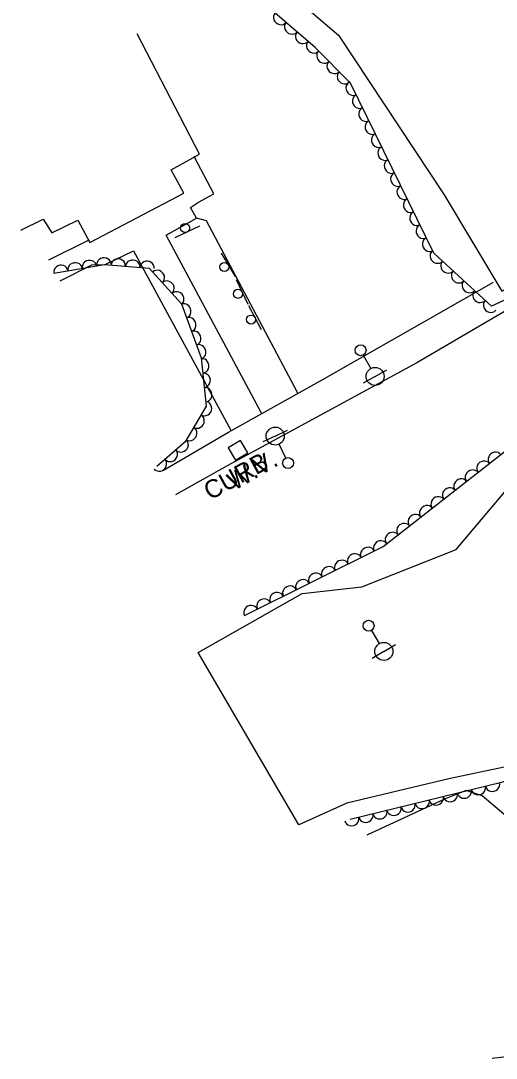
# Model space of a CAD drawing. Extents: x 1722896 to 1754269, y 648279 to 666297.
# Drawn here: x 1725162.1 to 1725293.4, y 656748.7 to 657035.2 of the extents above; entities that cross this region are included whole.
import ezdxf

# ---------------------------------------------------------------- set-up
doc = ezdxf.new("R2010")
doc.units = 0
for name, color, linetype in [('DESIGN - CENTERLINE - Proposed Text', 7, 'Continuous'), ('DESIGN - CONTOURS - Intermediate with optional Text', 7, 'Continuous'), ('DESIGN - PUBLIC HEARING - Shapes', 7, 'Continuous'), ('DESIGN - SCRATCH - User 1', 7, 'Continuous'), ('SURVEY - CENTERLINE - Preliminary', 7, 'Continuous'), ('SURVEY - CENTERLINE - Preliminary Text', 7, 'Continuous'), ('SURVEY - DTM - Breaklines', 7, 'Continuous'), ('SURVEY - VEGETATION - Features with Text', 7, 'Continuous')]:
    doc.layers.add(name, color=color, linetype=linetype)

msp = doc.modelspace()

# ---------------------------------------------------------------- linework, layer by layer
at = {"layer": 'DESIGN - CENTERLINE - Proposed Text'}
for points in [[(1725162.09, 656977.34), (1725168.28, 656980.41), (1725170.64, 656976.67), (1725177.81, 656980.17), (1725181.14, 656973.93), (1725207.11, 656987.54), (1725203.61, 656994.04), (1725211.4, 656998.37), (1725194.22, 657031.57)], [(1725228.55, 656926.87), (1725202.28, 656976), (1725210.6, 656980.65)], [(1725180.74, 656974.47), (1725169.79, 656969.12)], [(1725172.97, 656963.35), (1725181.68, 656967.82), (1725185.43, 656967.84), (1725193.25, 656971.63), (1725220.09, 656922.12)]]:
    msp.add_lwpolyline(points, dxfattribs=at)
at = {"layer": 'DESIGN - CONTOURS - Intermediate with optional Text'}
msp.add_line((1725222.08, 656916.58), (1725222.08, 656916.58), dxfattribs=at)
msp.add_lwpolyline([(1725219.35, 656917.31), (1725221.36, 656913.85), (1725224.81, 656915.86), (1725222.8, 656919.32), (1725219.35, 656917.31)], dxfattribs=at)
at = {"layer": 'DESIGN - PUBLIC HEARING - Shapes'}
for p, q in [((1725211.41, 656978.48), (1725204.65, 656975.24)), ((1725217.41, 656971.04), (1725221.27, 656964.61)), ((1725221.53, 656963.72), (1725224.78, 656956.97)), ((1725225.01, 656956.6), (1725228.51, 656949.97))]:
    msp.add_line(p, q, dxfattribs=at)
for centre in [(1725207.48, 656977.95), (1725218.3, 656967.17), (1725222.06, 656959.79), (1725225.69, 656952.69)]:
    msp.add_circle(centre, 1.25, dxfattribs=at)
at = {"layer": 'SURVEY - CENTERLINE - Preliminary'}
for points in [[(1725220.54, 657056.26), (1725249.82, 657031.18), (1725278.99, 656987.08), (1725294.93, 656960.48), (1725337.04, 656984.32), (1725355.92, 657002.3), (1725347.36, 657029.47), (1725333.65, 657057.33), (1725305.29, 657085.49), (1725285.46, 657108.75), (1725220.54, 657056.26)], [(1725211.04, 656860.76), (1725239.8, 656877.05), (1725256.25, 656878.92), (1725282.33, 656889.19), (1725301.73, 656912.24), (1725311.42, 656915.4), (1725338.36, 656911.9), (1725359.19, 656920.36), (1725368.5, 656904.89), (1725371.6, 656887.76), (1725358.67, 656881.14), (1725359.34, 656873.97), (1725339.38, 656862.59), (1725318.48, 656837.72), (1725302.51, 656830.54), (1725280.24, 656825.91), (1725252.08, 656819.18), (1725238.91, 656813.19), (1725211.04, 656860.76)]]:
    msp.add_lwpolyline(points, dxfattribs=at)
at = {"layer": 'SURVEY - CENTERLINE - Preliminary Text'}
for points in [[(1725549.38, 657135.48), (1725513.49, 657105.3), (1725471.68, 657072.67), (1725427.12, 657040.14), (1725377.39, 657005.82), (1725326.06, 656972.7), (1725271.47, 656940.69), (1725219.07, 656912.28), (1725204.85, 656904.26)], [(1725238.57, 656932.39), (1725213.34, 656979.93), (1725210.6, 656980.65), (1725209, 656983.6), (1725211.15, 656985.14), (1725215.42, 656987.35), (1725209.99, 656997.69)], [(1725201.52, 656911.09), (1725219.49, 656921.62), (1725245.31, 656936.04), (1725292.65, 656963)], [(1725464.13, 656811.54), (1725461.25, 656806.55), (1725458.02, 656803.74), (1725452.12, 656800.11), (1725438.36, 656794.63), (1725409.39, 656783.36), (1725391.32, 656778.7), (1725375, 656774.89), (1725367.83, 656774.04), (1725357.16, 656776.48), (1725342.38, 656782.53), (1725327.16, 656789.64), (1725318.33, 656796.85), (1725296.64, 656815.15), (1725289.47, 656821.17), (1725285.09, 656822.64), (1725279.04, 656820.25), (1725257.65, 656810.3)], [(1725292.23, 656748.73), (1725327.95, 656752.98), (1725364.89, 656756.8), (1725375.48, 656758.16)]]:
    msp.add_lwpolyline(points, dxfattribs=at)
at = {"layer": 'SURVEY - DTM - Breaklines'}
for p, q in [((1725256.65, 656942.89), (1725258.71, 656939.17)), ((1725259.92, 656936.98), (1725256.64, 656935.16)), ((1725259.92, 656936.98), (1725263.2, 656938.8)), ((1725232.34, 656920.5), (1725235.72, 656922.12)), ((1725232.34, 656920.5), (1725228.96, 656918.88)), ((1725235.25, 656914.41), (1725233.42, 656918.24)), ((1725258.91, 656866.86), (1725261.07, 656863.2)), ((1725262.34, 656861.05), (1725265.57, 656862.95)), ((1725262.34, 656861.05), (1725259.11, 656859.14))]:
    msp.add_line(p, q, dxfattribs=at)
for centre, radius in [((1725255.92, 656944.2), 1.5), ((1725259.92, 656936.98), 2.5), ((1725232.34, 656920.5), 2.5), ((1725235.9, 656913.06), 1.5), ((1725258.14, 656868.15), 1.5), ((1725262.34, 656861.05), 2.5)]:
    msp.add_circle(centre, radius, dxfattribs=at)
at = {"layer": 'SURVEY - VEGETATION - Features with Text'}
for points in [[(1725291.18, 657111.91), (1725326.1, 657083.38), (1725337.26, 657071.03), (1725346.29, 657049.3), (1725355.28, 657027.04), (1725360.66, 657009.82), (1725362.75, 657000.18), (1725357.16, 656991.63), (1725326.61, 656972.27), (1725292.02, 656956.35), (1725276.1, 656971.03), (1725253.1, 657017.98), (1725243.39, 657027.79), (1725217.32, 657050.26)], [(1725171.21, 656965.51), (1725185.21, 656967.86), (1725197.58, 656966.88), (1725206.46, 656957.06), (1725211.92, 656942.13), (1725213.32, 656928.75), (1725207.46, 656918.95), (1725199.7, 656912.09)], [(1725223.84, 656870.98), (1725262.11, 656890.03), (1725301.76, 656920.92), (1725328.71, 656923.12), (1725345.82, 656924.48), (1725360.29, 656925.54), (1725367.44, 656920.28), (1725373.75, 656898.57), (1725375.2, 656885.23), (1725358.4, 656869.39), (1725340.72, 656860.08), (1725318.94, 656834.01), (1725294.8, 656824.9), (1725253.01, 656814.68)]]:
    msp.add_lwpolyline(points, dxfattribs=at)
for centre, major_axis in [((1725233.83, 657036.03), (-1.52, 1.31)), ((1725236.86, 657033.42), (-1.52, 1.31)), ((1725239.89, 657030.81), (-1.52, 1.31)), ((1725242.92, 657028.2), (-1.52, 1.31)), ((1725245.77, 657025.39), (-1.41, 1.42)), ((1725248.58, 657022.54), (-1.41, 1.42)), ((1725251.39, 657019.7), (-1.41, 1.42)), ((1725253.79, 657016.56), (-0.88, 1.8)), ((1725255.55, 657012.97), (-0.88, 1.8)), ((1725257.31, 657009.38), (-0.88, 1.8)), ((1725259.07, 657005.79), (-0.88, 1.8)), ((1725260.83, 657002.19), (-0.88, 1.8)), ((1725262.59, 656998.6), (-0.88, 1.8)), ((1725264.35, 656995.01), (-0.88, 1.8)), ((1725266.11, 656991.42), (-0.88, 1.8)), ((1725267.87, 656987.83), (-0.88, 1.8)), ((1725269.63, 656984.23), (-0.88, 1.8)), ((1725271.39, 656980.64), (-0.88, 1.8)), ((1725273.15, 656977.05), (-0.88, 1.8)), ((1725274.91, 656973.46), (-0.88, 1.8)), ((1725277.05, 656970.15), (-1.47, 1.36)), ((1725177.12, 656966.5), (1.97, 0.33)), ((1725181.07, 656967.16), (1.97, 0.33)), ((1725185.01, 656967.83), (1.97, 0.33)), ((1725189, 656967.56), (1.99, -0.16)), ((1725192.99, 656967.24), (1.99, -0.16)), ((1725196.97, 656966.93), (1.99, -0.16)), ((1725279.99, 656967.44), (-1.47, 1.36)), ((1725173.18, 656965.84), (1.97, 0.33)), ((1725199.86, 656964.36), (1.34, -1.48)), ((1725282.93, 656964.73), (-1.47, 1.36)), ((1725202.54, 656961.4), (1.34, -1.48)), ((1725285.88, 656962.02), (-1.47, 1.36)), ((1725205.22, 656958.43), (1.34, -1.48)), ((1725288.82, 656959.31), (-1.47, 1.36)), ((1725207.2, 656955.04), (0.69, -1.88)), ((1725291.76, 656956.6), (-1.47, 1.36)), ((1725208.57, 656951.28), (0.69, -1.88)), ((1725209.95, 656947.53), (0.69, -1.88)), ((1725211.32, 656943.77), (0.69, -1.88)), ((1725212.16, 656939.89), (0.21, -1.99)), ((1725212.57, 656935.91), (0.21, -1.99)), ((1725212.99, 656931.93), (0.21, -1.99)), ((1725212.91, 656928.06), (-1.03, -1.72)), ((1725210.86, 656924.63), (-1.03, -1.72)), ((1725208.8, 656921.2), (-1.03, -1.72)), ((1725206.42, 656918.04), (-1.5, -1.33)), ((1725203.43, 656915.39), (-1.5, -1.33)), ((1725200.43, 656912.74), (-1.5, -1.33)), ((1725289.92, 656911.69), (1.58, 1.23)), ((1725293.07, 656914.15), (1.58, 1.23)), ((1725286.76, 656909.23), (1.58, 1.23)), ((1725283.61, 656906.77), (1.58, 1.23)), ((1725280.45, 656904.32), (1.58, 1.23)), ((1725277.3, 656901.86), (1.58, 1.23)), ((1725274.14, 656899.4), (1.58, 1.23)), ((1725267.83, 656894.48), (1.58, 1.23)), ((1725270.98, 656896.94), (1.58, 1.23)), ((1725264.67, 656892.03), (1.58, 1.23)), ((1725261.44, 656889.69), (1.79, 0.89)), ((1725254.28, 656886.13), (1.79, 0.89)), ((1725257.86, 656887.91), (1.79, 0.89)), ((1725250.7, 656884.35), (1.79, 0.89)), ((1725243.53, 656880.78), (1.79, 0.89)), ((1725247.11, 656882.57), (1.79, 0.89)), ((1725236.37, 656877.22), (1.79, 0.89)), ((1725239.95, 656879), (1.79, 0.89)), ((1725232.79, 656875.44), (1.79, 0.89)), ((1725225.63, 656871.87), (1.79, 0.89)), ((1725229.21, 656873.65), (1.79, 0.89)), ((1725292.33, 656824.3), (-1.94, -0.48)), ((1725280.68, 656821.45), (-1.94, -0.48)), ((1725284.56, 656822.4), (-1.94, -0.48)), ((1725288.45, 656823.35), (-1.94, -0.48)), ((1725269.02, 656818.59), (-1.94, -0.48)), ((1725272.91, 656819.54), (-1.94, -0.48)), ((1725276.79, 656820.49), (-1.94, -0.48)), ((1725257.37, 656815.74), (-1.94, -0.48)), ((1725261.25, 656816.69), (-1.94, -0.48)), ((1725265.14, 656817.64), (-1.94, -0.48)), ((1725253.48, 656814.79), (-1.94, -0.48))]:
    msp.add_ellipse(centre, major_axis=major_axis, ratio=0.940188, start_param=0, end_param=3.141593, dxfattribs=at)

# ---------------------------------------------------------------- texts
at = {"layer": 'DESIGN - CONTOURS - Intermediate with optional Text'}
msp.add_text('W.V.', height=5, rotation=30.1727, dxfattribs=at).set_placement((1725221.04, 656905.34))
at = {"layer": 'DESIGN - SCRATCH - User 1'}
msp.add_text('CURB', height=5, rotation=28.8563, dxfattribs=at).set_placement((1725214.38, 656902.69))

doc.saveas('drawing.dxf')
